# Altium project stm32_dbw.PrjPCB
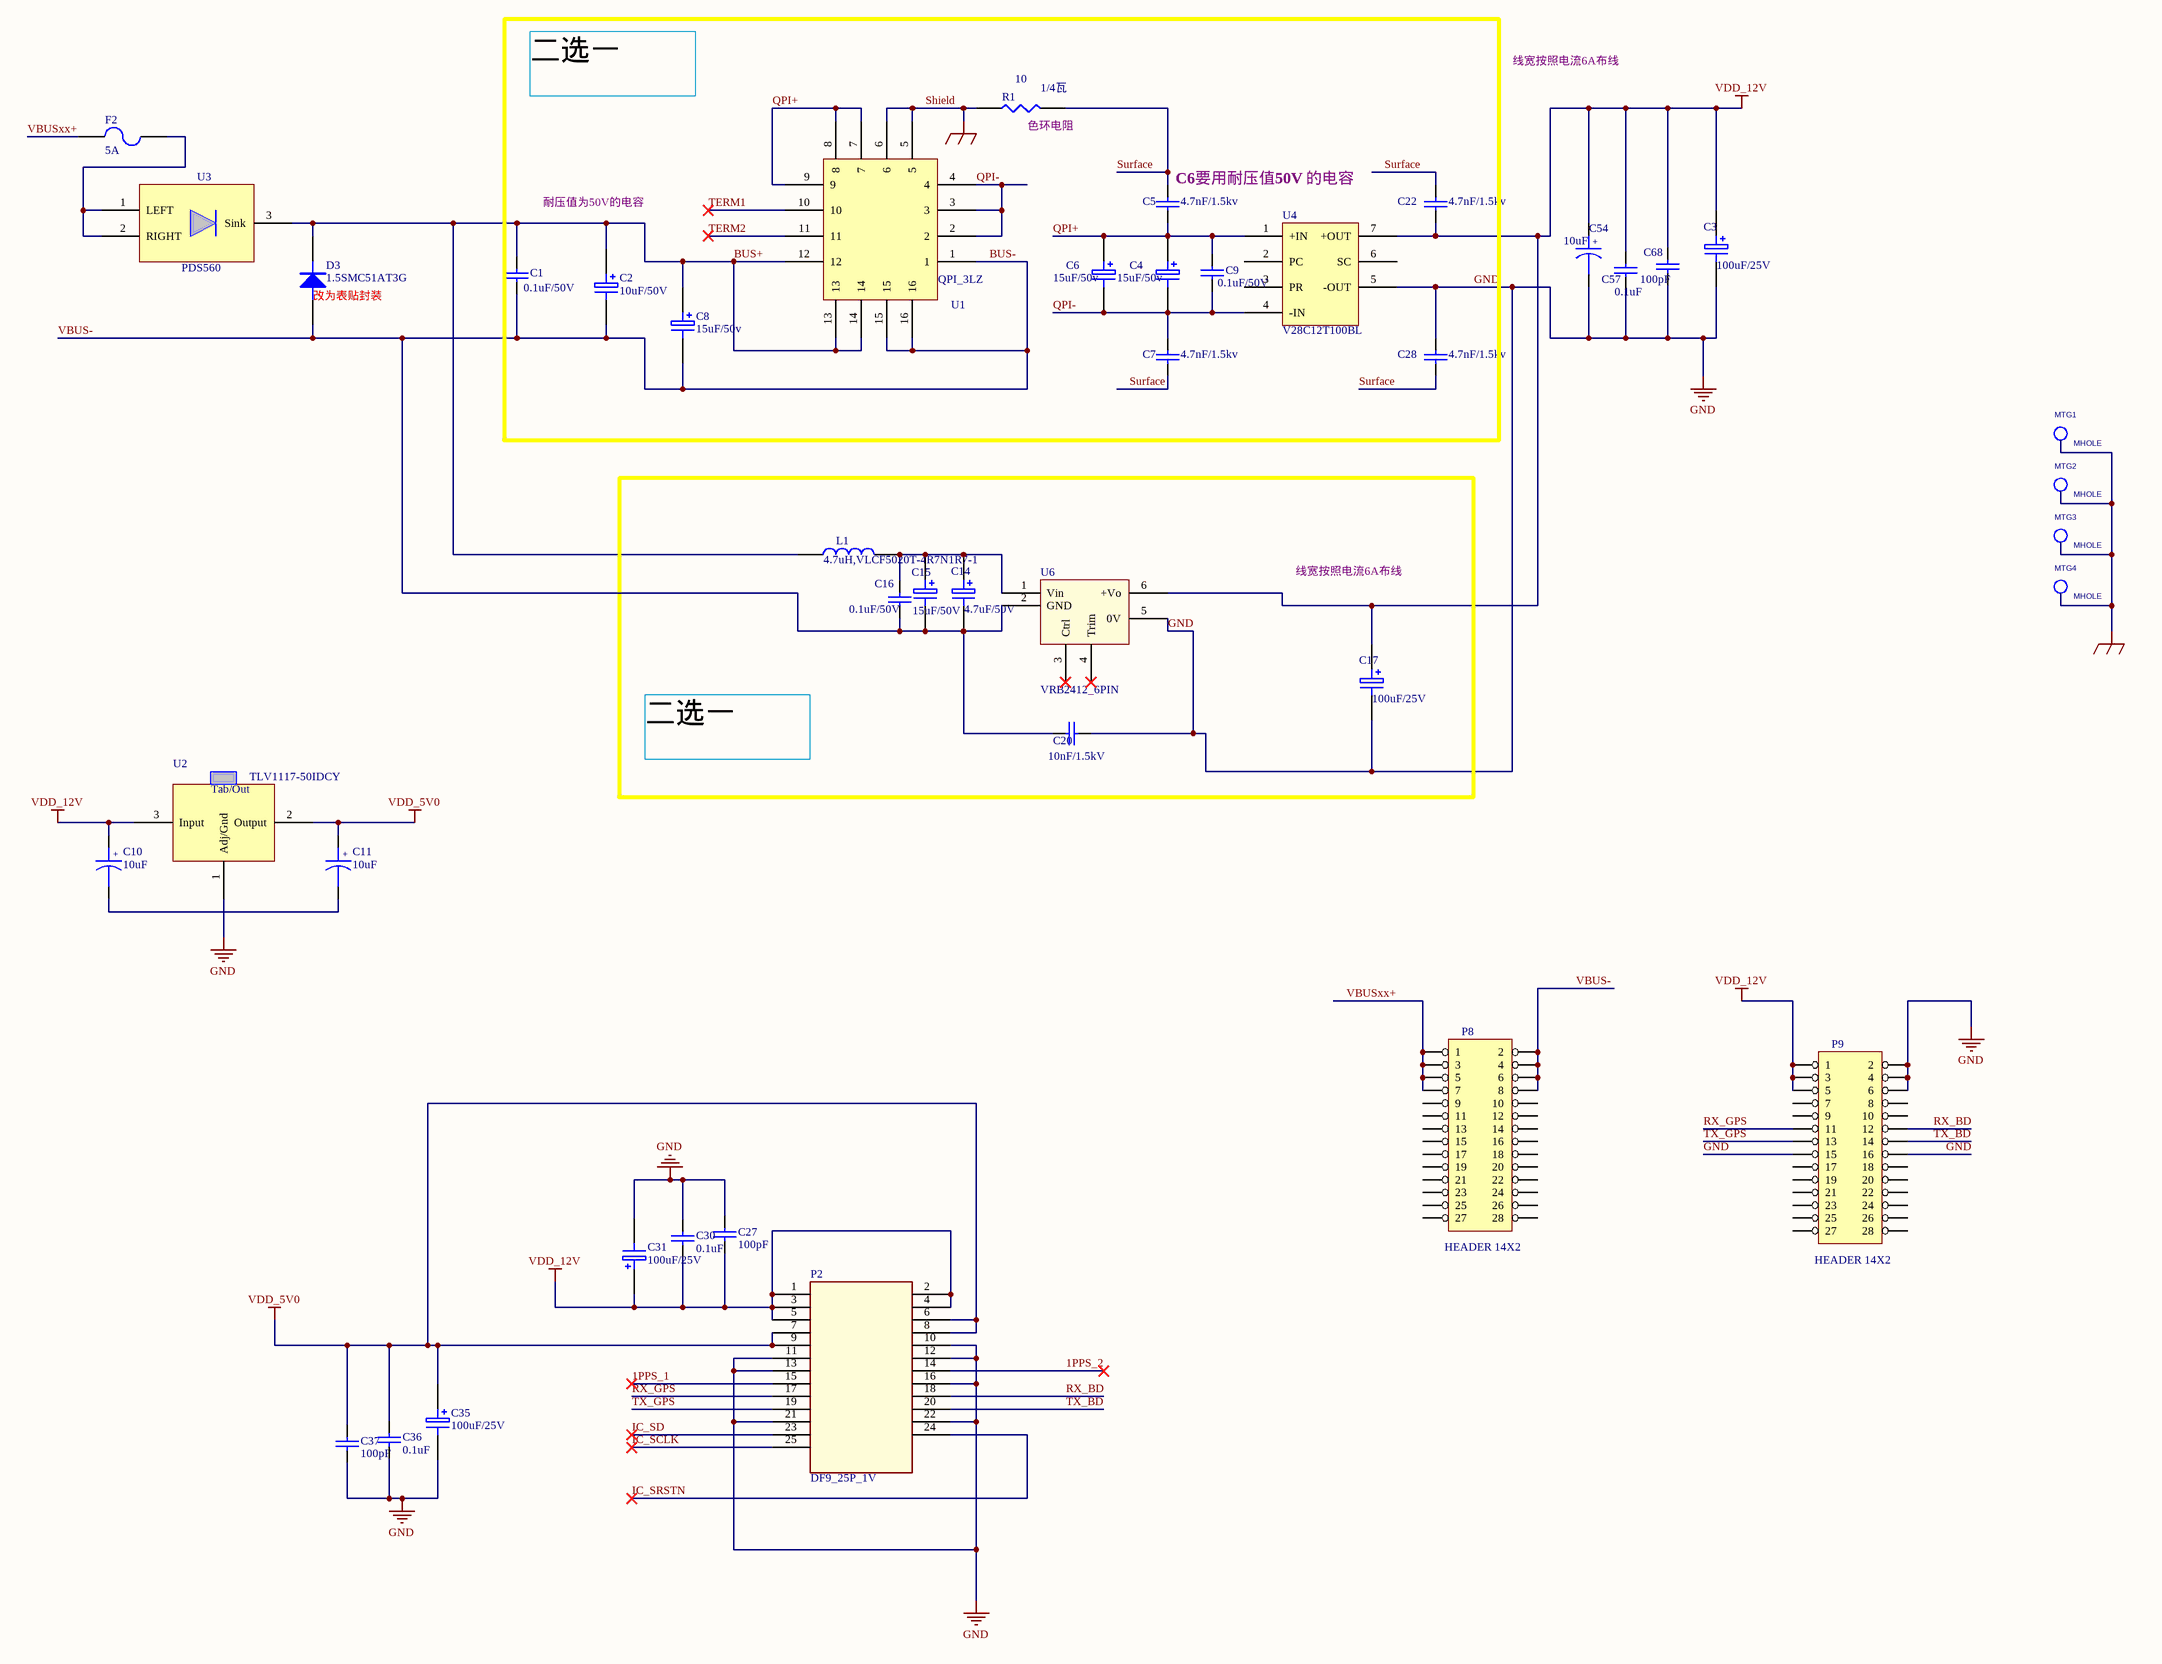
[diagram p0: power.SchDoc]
2 sheets, 96 parts. Net scope: global (net labels, ports and power ports of the same name join across sheets).
Sheets:
  power.SchDoc
  mcu.SchDoc

## Sheet power.SchDoc
size A2

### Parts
(Parts that share a designator on the sheet are numbered #1, #2 ... from top to bottom, then left to right.)
C1  0.1uF/50V  [0603C]
C2  10uF/50V  [7343T]
C3  100uF/25V  [7343T]
C4  15uF/50v  [7343T]
C5  4.7nF/1.5kv  [1812C]
C6  15uF/50v  [7343T]
C7  4.7nF/1.5kv  [1812C]
C8  15uF/50v  [7343T]
C9  0.1uF/50V  [0603C]
C10  10uF  [3528T]
C11  10uF  [3528T]
C14  4.7uF/50V  [7343T]
C15  15uF/50V  [7343T]
C16  0.1uF/50V  [0603C]
C17  100uF/25V  [7343T]
C20  10nF/1.5kV  [1812C]
C22  4.7nF/1.5kv  [1812C]
C27  100pF  [0603C]
C28  4.7nF/1.5kv  [1812C]
C30  0.1uF  [0603C]
C31  100uF/25V  [7343T]
C35  100uF/25V  [7343T]
C36  0.1uF  [0603C]
C37  100pF  [0603C]
C54  10uF  [3528T]
C57  0.1uF  [0603C]
C68  100pF  [0603C]
D3  1.5SMC51AT3G  [1.5SMC51AT3G]
F2  5A  [1812F]
L1  4.7uH,VLCF5020T-4R7N1R7-1  [5MMX5MM]
MTG1#1  MHOLE  [MTGH200C125D_PL]  (no BOM)
MTG2#1  MHOLE  [MTGH200C125D_PL]  (no BOM)
MTG3#1  MHOLE  [MTGH200C125D_PL]  (no BOM)
MTG4#1  MHOLE  [MTGH200C125D_PL]  (no BOM)
P2  DF9_25P_1V  [DF9_25P_1V_25PIN]
P8  HEADER 14X2  [HEADER14X2-2r54]
P9  HEADER 14X2  [HEADER14X2-2r54]
R1  10  [AXIAL-0.4]
U1  QPI_3LZ  [QPI_3LZ]
U2  TLV1117-50IDCY  [SOT-223-DCY]
U3  PDS560  [PDS560]
U4  V28C12T100BL  [V24C5]
U6  VRB2412_6PIN  [VRB2412_6PIN]

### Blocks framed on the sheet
C6要用耐压值50V 的电容: C1 C2 C4-C9 C22 C28 R1 U1 U4
线宽按照电流6A布线: C14-C17 C20 L1 U6

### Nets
GND: C3.2 C17.2 C20.2 C27.2 C28.1 C30.2 C31.2 C35.2 C36.2 C37.2 C54.2 C57.2 C68.2 P2.10 P2.11 P2.12 P2.13 P2.16 P2.21 P2.22 P9.2 P9.4 P9.6 P9.15 P9.16 U2.1(Adj/Gnd) U4.5(-OUT) U6.5(0V)
Shield: MTG1#1.1(TP) MTG2#1.1(TP) MTG3#1.1(TP) MTG4#1.1(TP) R1.1 U1.5 U1.6  [also labelled EARTH]
VDD_5V0: C11.1 C35.1 C36.1 C37.1 P2.6 P2.7 P2.8 P2.9 U2.2(Output)
VDD_12V: C3.1 C10.1 C17.1 C22.2 C27.1 C30.1 C31.1 C54.1 C57.1 C68.1 P2.1 P2.2 P2.3 P2.4 P2.5 P9.1 P9.3 P9.5 U2.3(Input) U4.7(+OUT) U6.6(+Vo)
1PPS_1: P2.15
1PPS_2: P2.14
BUS+: C1.1 C2.1 C8.1 D3.2(K) L1.1 U1.12 U1.13 U1.14 U3.3(Sink)
BUS-: C1.2 C2.2 C8.2 C14.2 C15.2 C16.2 C20.1 D3.1(A) P8.2 P8.4 P8.6 P8.8 U1.1 U1.15 U1.16 U6.2(GND)  [also labelled VBUS-]
IC_SCLK: P2.25
IC_SD: P2.23
IC_SRSTN: P2.24
QPI+: C4.1 C5.2 C6.1 C9.1 U1.7 U1.8 U1.9 U4.1(+IN)
QPI-: C4.2 C6.2 C7.1 C9.2 U1.2 U1.3 U1.4 U4.4(-IN)
RX_BD: P2.18 P9.12
RX_GPS: P2.17 P9.11
Surface: C5.1 C7.2 C22.1 C28.2 R1.2
TERM1: U1.10
TERM2: U1.11
TX_BD: P2.20 P9.14
TX_GPS: P2.19 P9.13
VBUSxx+: F2.1 P8.1 P8.3 P8.5 P8.7
NetC10_2: C10.2 C11.2
NetC14_1: C14.1 C15.1 C16.1 L1.2 U6.1(Vin)
NetF2_2: F2.2 U3.1(LEFT) U3.2(RIGHT)

Not connected (* = marked no-connect by the designer): P8 9 10 11 12 13 14 15 16 17 18 19 20 21 22 23 24 25 26 27 28; P9 7 8 9 10 17 18 19 20 21 22 23 24 25 26 27 28; U4 2(PC) 3(PR) 6(SC); U6 3(Ctrl)* 4(Trim)*

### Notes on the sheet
- 二选一
- (near R1) 1/4瓦
- 线宽按照电流6A布线
- (near R1) 色环电阻
- 耐压值为50V的电容
- (near D3) 改为表贴封装

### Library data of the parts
C1 C5 C7 C9 C16 C20 C22 C27 C28 C30 C36 C37 C57 C68 = CAP: Capacitor
C2-C4 C6 C8 C14 C15 C17 C31 C35 = ELECTRO1: Electrolytic Capacitor
C10 C11 C54 = CAPACITOR POL: Capacitor
D3 = DIODE
F2 = FUSE2: Fuse
L1 = INDUCTOR
P2 = HDR_25PIN
R1 = RES1
U1 = QPI_FILTER
U2 = LM1117IMP-5.0/NOPB
U4 = VICOR_DIANYUAN

## Sheet mcu.SchDoc
size A2
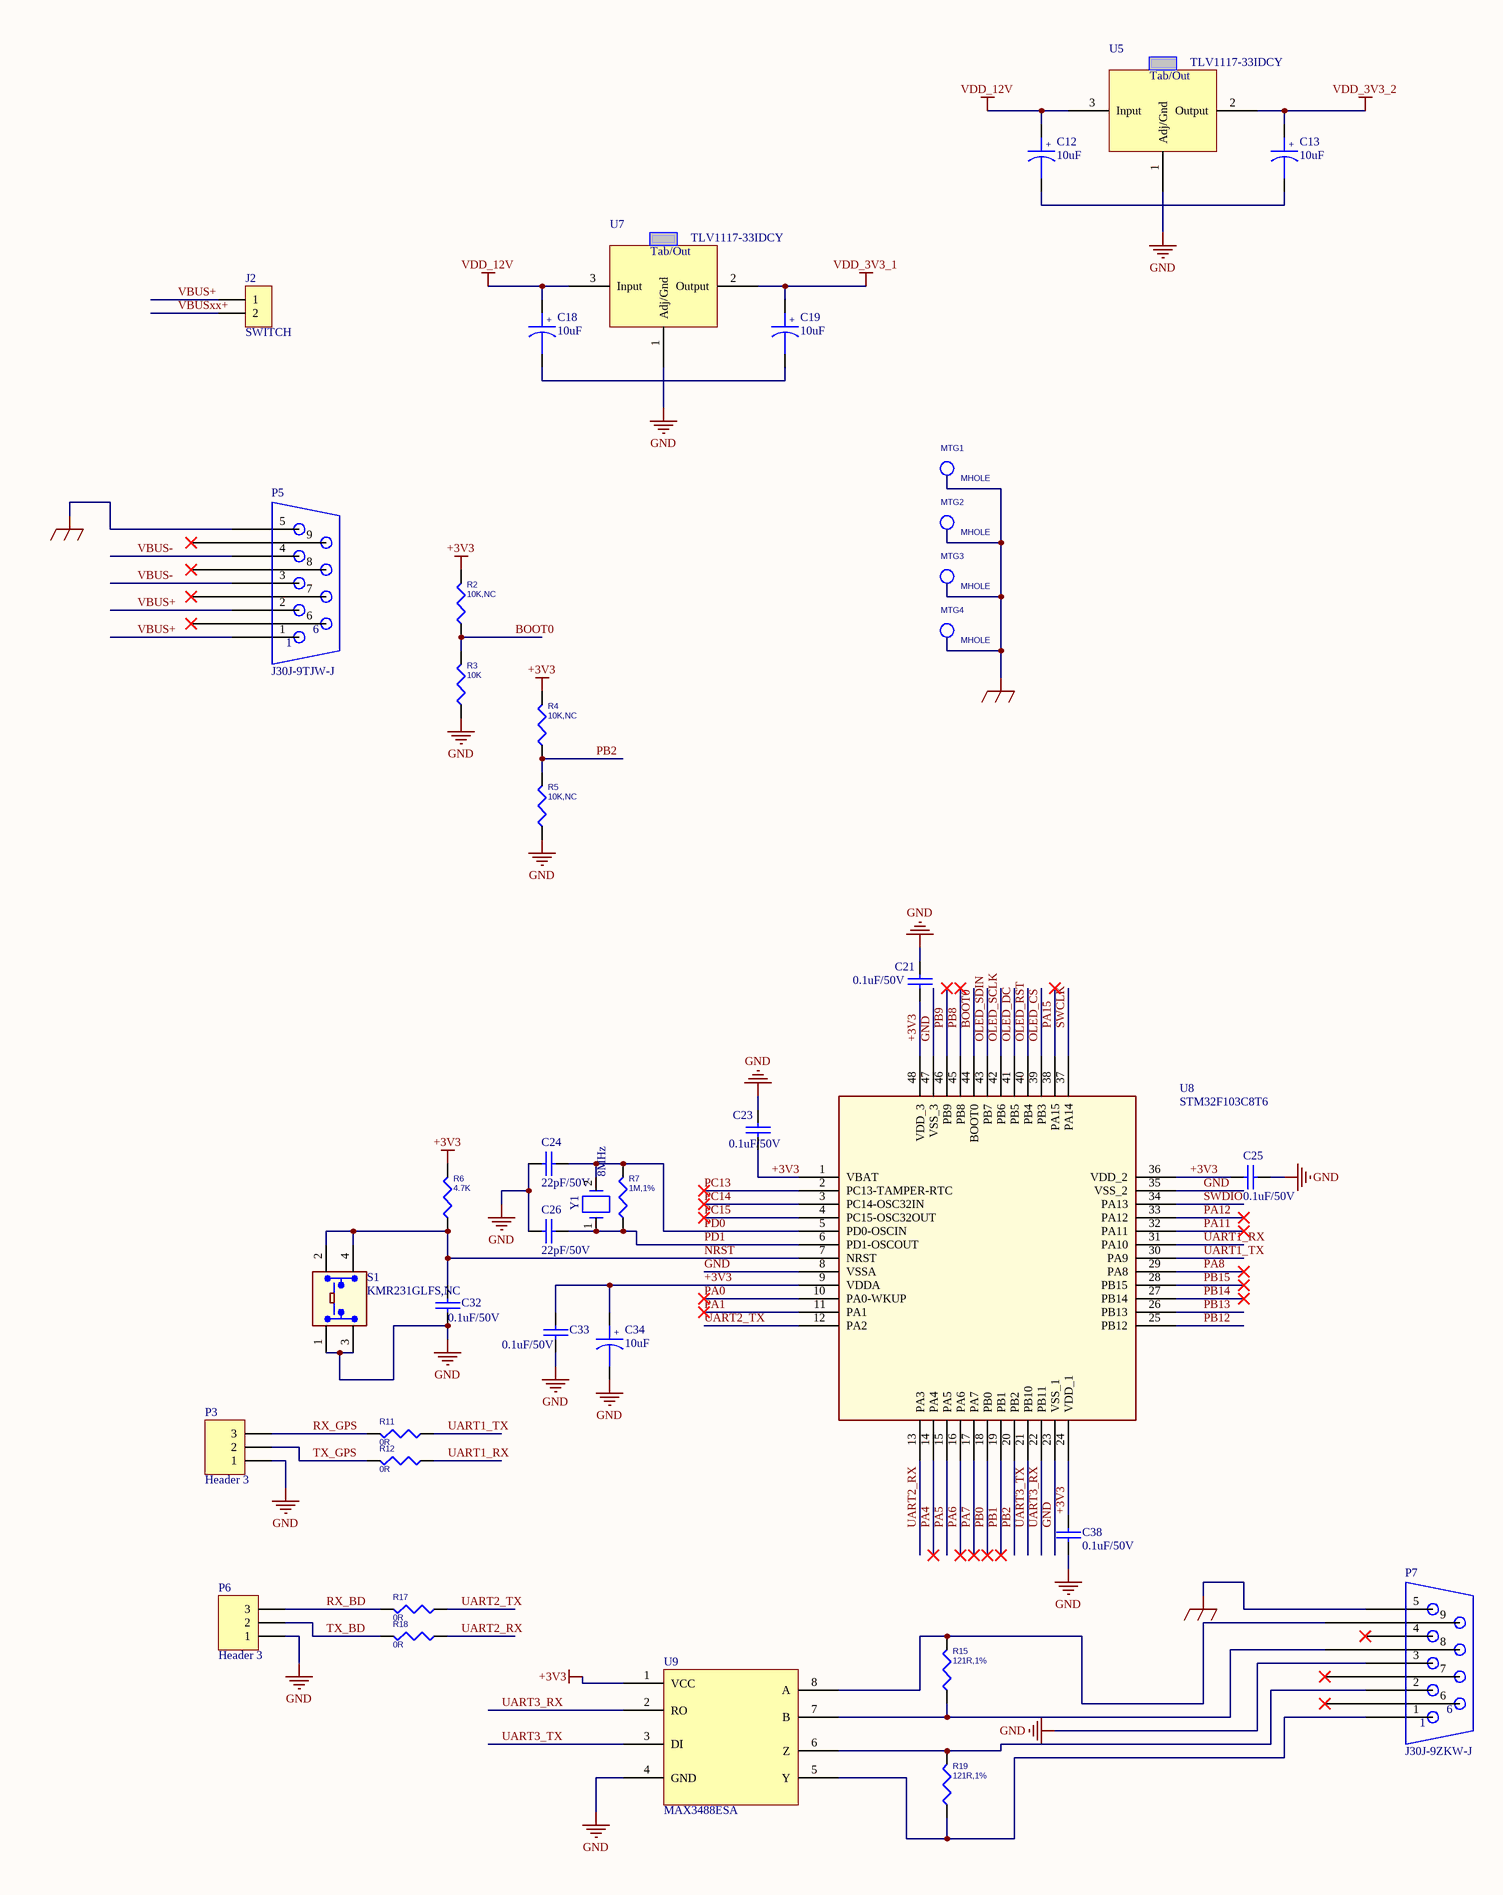
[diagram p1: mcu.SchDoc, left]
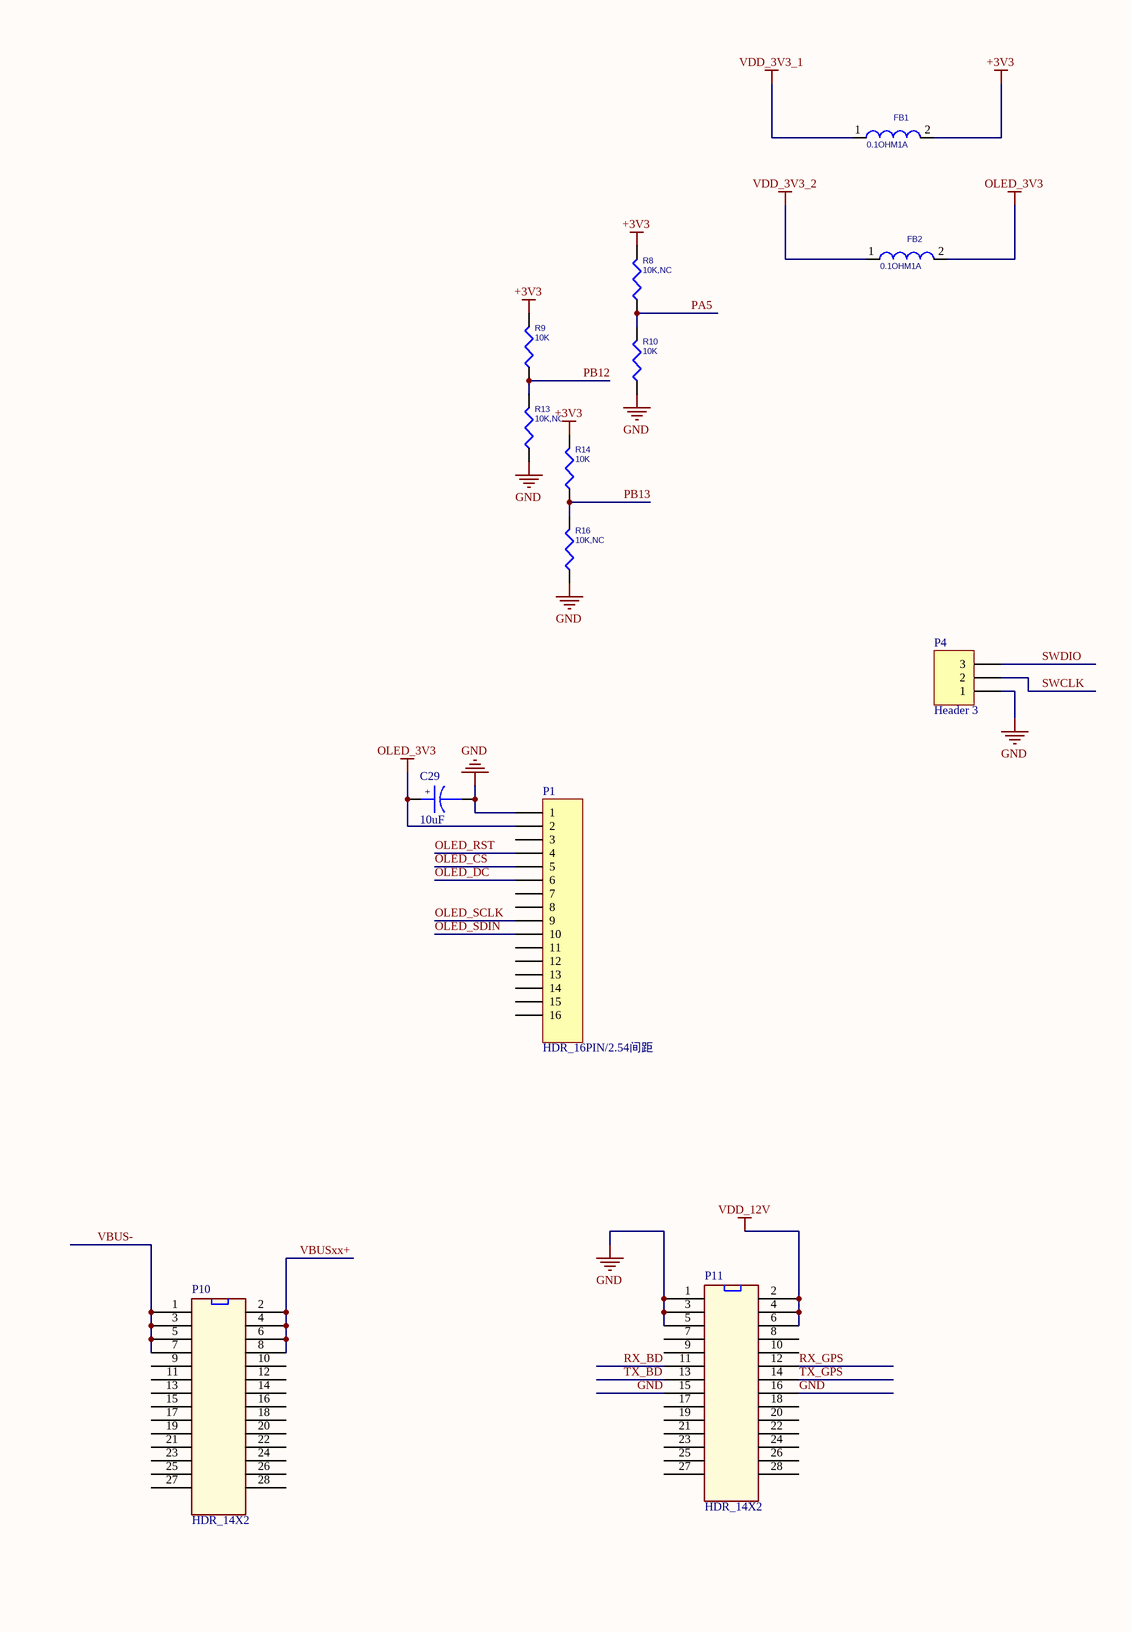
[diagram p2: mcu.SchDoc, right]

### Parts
(Parts that share a designator on the sheet are numbered #1, #2 ... from top to bottom, then left to right.)
C12  10uF  [3528T]
C13  10uF  [3528T]
C18  10uF  [3528T]
C19  10uF  [3528T]
C21  0.1uF/50V  [0603C]
C23  0.1uF/50V  [0603C]
C24  22pF/50V  [0603C]
C25  0.1uF/50V  [0603C]
C26  22pF/50V  [0603C]
C29  10uF  [3528T]
C32  0.1uF/50V  [0603C]
C33  0.1uF/50V  [0603C]
C34  10uF  [3528T]
C38  0.1uF/50V  [0603C]
FB1  0.1OHM1A  [SM-7351-IND-0805]
FB2  0.1OHM1A  [SM-7351-IND-0805]
J2  SWITCH  [28V]
MTG1#2  MHOLE  [MTGH200C125D_PL]  (no BOM)
MTG2#2  MHOLE  [MTGH200C125D_PL]  (no BOM)
MTG3#2  MHOLE  [MTGH200C125D_PL]  (no BOM)
MTG4#2  MHOLE  [MTGH200C125D_PL]  (no BOM)
P1  HDR_16PIN/2.54间距  [HDR_16PIN]
P3  Header 3  [HDR1X3]
P4  Header 3  [HDR1X3]
P5  J30J-9TJW-J  [J30J-9TJW-J]
P6  Header 3  [HDR1X3]
P7  J30J-9ZKW-J  [J30J-9ZKW-J]
P10  HDR_14X2  [HDR_14X2]
P11  HDR_14X2  [HDR_14X2]
R2  10K,NC  [R0603]
R3  10K  [R0603]
R4  10K,NC  [R0603]
R5  10K,NC  [R0603]
R6  4.7K  [R0603]
R7  1M,1%  [R0603]
R8  10K,NC  [R0603]
R9  10K  [R0603]
R10  10K  [R0603]
R11  0R  [R0603]
R12  0R  [R0603]
R13  10K,NC  [R0603]
R14  10K  [R0603]
R15  121R,1%  [R0603]
R16  10K,NC  [R0603]
R17  0R  [R0603]
R18  0R  [R0603]
R19  121R,1%  [R0603]
S1  KMR231GLFS,NC  [SW4SMD_63X161LS]
U5  TLV1117-33IDCY  [SOT-223-DCY]
U7  TLV1117-33IDCY  [SOT-223-DCY]
U8  STM32F103C8T6  [LQFP-48PIN]
U9  MAX3488ESA  [8 SO]
Y1  8MHz  [XTAL1]

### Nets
+3V3: C21.2 C23.2 C25.2 C33.2 C34.1 C38.2 FB1.2 R2.2 R4.2 R6.2 R8.2 R9.2 R14.2 U8.1(VBAT) U8.9(VDDA) U8.24(VDD_1) U8.36(VDD_2) U8.48(VDD_3) U9.1(VCC)
EARTH: MTG1#2.1(TP) MTG2#2.1(TP) MTG3#2.1(TP) MTG4#2.1(TP) P5.5 P7.5  [project net Shield]
GND: C21.1 C23.1 C24.1 C25.1 C26.1 C29.2 C32.1 C33.1 C34.2 C38.1 P1.1 P3.1 P4.1 P6.1 P7.3 P11.1 P11.3 P11.5 P11.15 P11.16 R3.1 R5.1 R10.1 R13.1 R16.1 S1.1(A1) S1.3(A3) U5.1(Adj/Gnd) U7.1(Adj/Gnd) U8.8(VSSA) U8.23(VSS_1) U8.35(VSS_2) U8.47(VSS_3) U9.4(GND)
OLED_3V3: C29.1 FB2.2 P1.2
VDD_3V3_1: C19.1 FB1.1 U7.2(Output)
VDD_3V3_2: C13.1 FB2.1 U5.2(Output)
VDD_12V: C12.1 C18.1 P11.2 P11.4 P11.6 U5.3(Input) U7.3(Input)
BOOT0: R2.1 R3.2 U8.44(BOOT0)
NRST: C32.2 R6.1 S1.2(A2) S1.4 U8.7(NRST)
OLED_CS: P1.5 U8.39(PB3)
OLED_DC: P1.6 U8.41(PB5)
OLED_RST: P1.4 U8.40(PB4)
OLED_SCLK: P1.9 U8.42(PB6)
OLED_SDIN: P1.10 U8.43(PB7)
PA0: U8.10(PA0-WKUP)
PA1: U8.11(PA1)
PA4: U8.14(PA4)
PA5: R8.1 R10.2 U8.15(PA5)
PA6: U8.16(PA6)
PA7: U8.17(PA7)
PA8: U8.29(PA8)
PA11: U8.32(PA11)
PA12: U8.33(PA12)
PA15: U8.38(PA15)
PB0: U8.18(PB0)
PB1: U8.19(PB1)
PB2: R4.1 R5.2 U8.20(PB2)
PB8: U8.45(PB8)
PB9: U8.46(PB9)
PB12: R9.1 R13.2 U8.25(PB12)
PB13: R14.1 R16.2 U8.26(PB13)
PB14: U8.27(PB14)
PB15: U8.28(PB15)
PC13: U8.2(PC13-TAMPER-RTC)
PC14: U8.3(PC14-OSC32IN)
PC15: U8.4(PC15-OSC32OUT)
PD0: C24.2 R7.2 U8.5(PD0-OSCIN) Y1.2
PD1: C26.2 R7.1 U8.6(PD1-OSCOUT) Y1.1
RX_BD: P6.3 P11.11 R17.2
RX_GPS: P3.3 P11.12 R11.2
SWCLK: P4.2 U8.37(PA14)
SWDIO: P4.3 U8.34(PA13)
TX_BD: P6.2 P11.13 R18.2
TX_GPS: P3.2 P11.14 R12.2
UART1_RX: R12.1 U8.31(PA10)
UART1_TX: R11.1 U8.30(PA9)
UART2_RX: R18.1 U8.13(PA3)
UART2_TX: R17.1 U8.12(PA2)
UART3_RX: U8.22(PB11) U9.2(RO)
UART3_TX: U8.21(PB10) U9.3(DI)
VBUS+: J2.1 P5.1 P5.2
VBUS-: P5.3 P5.4 P10.1 P10.3 P10.5 P10.7  [project net BUS-]
VBUSxx+: J2.2 P10.2 P10.4 P10.6 P10.8
NetC12_2: C12.2 C13.2
NetC18_2: C18.2 C19.2
NetP7_1: P7.1 R19.1 U9.5(Y)
NetP7_2: P7.2 R19.2 U9.6(Z)
NetP7_8: P7.8 R15.1 U9.7(B)
NetP7_9: P7.9 R15.2 U9.8(A)

Not connected (* = marked no-connect by the designer): P1 3 7 8 11 12 13 14 15 16; P5 6* 7* 8* 9*; P7 4* 6* 7*; P10 9(5) 10(30) 11(6) 12(31) 13(7) 14(32) 15(8) 16(33) 17 18 19 20 21 22 23 24 25 26 27 28; P11 7(4) 8(29) 9(5) 10(30) 17 18 19 20 21 22 23 24 25 26 27 28

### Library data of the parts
C12 C13 C18 C19 C29 C34 = CAPACITOR POL: Capacitor
C21 C23-C26 C32 C33 C38 = CAP: Capacitor
FB1 FB2 = FER_180_200_0: FERRITE 800MA 150 OHM 0805 SMD; PartName: FerriteBead150ohm800mA; Mfr: Steward; MfrNum: LI0805H151R-10; TIIntPartnumber: 1L0010; Manufacturer: Laird-Signal Integrity Products; Vendor: Digikey; Impedance @ Frequency: 150 Ohm @ 100MHz; DC Resistance (DCR): 150 mOhm Max; Filter Type: Differential Mode - Single
J2 = CON2: Connector
P1 = HDR_16PIN
P3 P4 P6 = Header 3: Header, 3-Pin
P5 P7 = J30J-9TJN-J
R2-R19 = RES_0_1/16W_1%_0402: RES 0.0 OHM,0603,DNI; Manufacturer: Yageo; Manufacturer Part Number: RC0402JR-070RL; Resistance (Ohms): 0.0; Power (Watts): 0.063W, 1/16W; Tolerance: Jumper
S1 = KMR2: Microminiature Tact Switch for SMT; Manufacturer: C&K Components; Circuit: SPST-NO; Switch Function: Off-Mom; Contact Rating @ Voltage: 0.05A @ 32VDC; Actuator Type: Standard; Actuator Height off PCB, from Pins: 1.90mm; Actuator Orientation: Top Actuated; Outline: 4.60mm x 2.80mm; Illumination: Non-Illuminated; Operating Force: 300gf; Switch Travel: 0.25mm; Mechanical Life: 150,000 Cycles
U5 U7 = LM1117IMP-5.0/NOPB
U8 = STM32_48PIN
U9 = MAX3488
Y1 = CRYS_24MHz_SCC: CRYSTAL 24.000MHZ 18PF SMD; Manufacturer: TXC CORPORATION; Manufacturer Part Number: 7A-24.000MAAJ-T; Frequency: 24MHz; Frequency Stability: ?0ppm; ESR (Equivalent Series Resistance): 50 Ohm; Operating Mode: Fundamental

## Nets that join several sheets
GND: power (28 pins), mcu (34 pins)
Shield: power (7 pins), mcu (6 pins)
VDD_12V: power (21 pins), mcu (7 pins)
BUS-: power (16 pins), mcu (6 pins)
RX_BD: power (P2.18 P9.12), mcu (P6.3 P11.11 R17.2)
RX_GPS: power (P2.17 P9.11), mcu (P3.3 P11.12 R11.2)
TX_BD: power (P2.20 P9.14), mcu (P6.2 P11.13 R18.2)
TX_GPS: power (P2.19 P9.13), mcu (P3.2 P11.14 R12.2)
VBUSxx+: power (5 pins), mcu (5 pins)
